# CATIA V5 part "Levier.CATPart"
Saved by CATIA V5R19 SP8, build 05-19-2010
Part number: Levier
Nomenclature: 4
Bounding box of the stored display mesh (mm): x -228 to 228, y -20.3 to 246.7, z -26.3 to 20.3
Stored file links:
  C:\Users\rphgr\Desktop\0_Tapis_TC520B_vitesse\Levier.CATPart
  D:\Documents\1_Travail\1 - ac-limoges.fr\ac-limoges.fr\Emmanuel Maynard - STI2D_Turgot\3 - Supports\Tapis de course TC520B\Tapis de course TC520B_Ca\0_Tapis_TC520B.CATProduct
  D:\Documents\1_Travail\1 - ac-limoges.fr\ac-limoges.fr\Emmanuel Maynard - STI2D_Turgot\3 - Supports\Tapis de course TC520B\Tapis de course TC520B_Ca\CE_Ecrou_Verin.CATPart
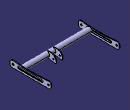
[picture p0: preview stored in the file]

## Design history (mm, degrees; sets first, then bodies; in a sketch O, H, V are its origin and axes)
SheetMetalParameters1: Thickness 5, BendRadius 4, KFactor 0.30103 {= log(min(100,max(20*SheetMetalParameters1.BendRadius,SheetMetalParameters1.Thickness)/SheetMetalParameters1.Thickness))/log(100)/2}, ReliefRadialLength 1, ReliefAxialLength 2, MinimumBendRadius 0
AxisSystem1: origin (0, 0, 0), X (1, 0, 0), Y (0, 1, 0), Z (0, 0, 1)
Set1
  DatumSurface1
  DatumCurve1
Set2
  Plane1: type Offset, RefPlane YZ plane of AxisSystem1, Offset 225.5, reversed
Body1 (main body)
  Sketch1 on Plane1, origin (-225.5, 0, 0), H (0, 1, 0), V (0, 0, 1)
    point P1 (4.7, 20.3)
    point P2 (113.2, 0)
    line L1 (246.7, 7.3) -> (246.7, -7.3)
    line L2 (233.7, -20.3) -> (-7.3, -20.3)
    line L3 (-20.3, -7.3) -> (-20.3, 7.3)
    line L4 (-7.3, 20.3) -> (4.7, 20.3)
    point P3 (-20.3, -20.3)
    arc A1 centre (113.2, 998.2999) radius 984 from (4.7, 20.3) to (221.7, 20.3) ccw
    point P4 (113.2, 998.2999)
    point P5 (221.7, 20.3)
    point P6 (4.7, 20.3)
    line L5 (221.7, 20.3) -> (233.7, 20.3)
    arc A2 centre (233.7, -7.3) radius 13 from (246.7, -7.3) to (233.7, -20.3) cw
    arc A3 centre (-7.3, -7.3) radius 13 from (-7.3, -20.3) to (-20.3, -7.3) cw
    arc A4 centre (-7.3, 7.3) radius 13 from (-20.3, 7.3) to (-7.3, 20.3) cw
    arc A5 centre (233.7, 7.3) radius 13 from (246.7, 7.3) to (233.7, 20.3) ccw
    distance L1 L3 = 267
    radius A2 = 13
    radius A3 = 13
    radius A4 = 13
    radius A5 = 13
    radius A1 = 984
    distance P4 P2 H = 0
    coincidence: P2 H, L4 P5, L4 L5, L2 P3, L3 P3, P6 P1
    vertical: L1 V, L3 V
    horizontal: L2 H, L4 H, L5 H
    equidistance: L1 L3 P2, L2 L4 P2
    tangency: A2 L1, A2 L2, A3 L2, A3 L3, A4 L3, A4 L4, A5 L1, A5 L5
  Wall1: Thickness 5, Profile Sketch1
  Plane2: type Offset, RefPlane YZ plane of AxisSystem1, Offset 225.5, reversed
  Sketch2 on face of Wall1, origin (-220.5, 0, 0), H (0, 1, 0), V (0, 0, 1)
    construction line L1 (38.2, 0) -> (188.2, 0)
    point P1 (38.2, 0)
    line L2 (38.2, 7) -> (188.2, 7)
    line L3 (188.2, -7) -> (38.2, -7)
    arc A1 centre (188.2, 0) radius 7 from (188.2, 7) to (188.2, -7) cw
    arc A2 centre (38.2, 0) radius 7 from (38.2, -7) to (38.2, 7) cw
    reference intersected line E1 (-20.3, -7.3) -> (-20.3, 7.3) from face of Wall1
    distance L1 L2 = 7
    length L1 = 150
    distance P1 E1 = 58.5
    coincidence: P1 H
    horizontal: L1 H
    tangency: A1 L2, A2 L2, A1 L3, A2 L3
  Sketch3 on face of Wall1, origin (-220.5, 0, 0), H (0, -1, 0), V (0, 0, 1)
    construction line L1 (-188.2, 0) -> (-38.2, 0)
    point P1 (-188.2, 0)
    point P2 (-38.2, 0)
    line L2 (-188.2, 0.5) -> (-38.2, 0.5)
    line L3 (-38.2, -0.5) -> (-188.2, -0.5)
    arc A1 centre (-38.2, 0) radius 0.5 from (-38.2, 0.5) to (-38.2, -0.5) cw
    arc A2 centre (-188.2, 0) radius 0.5 from (-188.2, -0.5) to (-188.2, 0.5) cw
    reference projected arc E1 centre (-38.2, 0) radius 7 from (-38.2, -7) to (-38.2, 7) ccw from Sketch2.A2
    reference projected arc E2 centre (-188.2, 0) radius 7 from (-188.2, 7) to (-188.2, -7) ccw from Sketch2.A1
    distance L1 L2 = 0.5
    coincidence: P1 H
    horizontal: L1 H
    tangency: A1 L2, A2 L2, A1 L3, A2 L3
    concentricity: P2 E1, A2 E2
  d_Stamp1: NewRoot_AttribNormalisation "No Standard", Stamp_FilletRadius 1
  Sketch4 on face of Wall1, origin (-225.5, 0.1839, -4.3322), H (0, 1, 0), V (0, 0, -1)
    point P1 (-0.1839, -4.3322)
    reference projected point E1 (-0.1839, -4.3322) from edge [XY plane of AxisSystem1 | ZX plane of AxisSystem1]
    coincidence: P1 E1
  Hole1: placed by Sketch4, at (-225.5, 0, 0) direction (1, 0, 0), diameter 12, through (limit type 3)
  Sketch5 on face of Wall1, origin (-225.5, 226.4946, 0.7211), H (0, 1, 0), V (0, 0, -1)
    point P1 (3.5054, 0.7211)
    reference intersected line E1 through (0, 0.7211) direction (1, 0) from XY plane of AxisSystem1
    reference projected point E2 (-226.4946, 0.7211) from axis of face of Hole1
    distance E2 P1 = 230
    coincidence: P1 E1
  Hole2: placed by Sketch5, at (-225.5, 230, 0) direction (1, 0, 0), diameter 12, through (limit type 3)
  Mirror1: of the body so far, about YZ plane of AxisSystem1
  Sketch6 on YZ plane of AxisSystem1, origin (0, 0, 0), H (0, 1, 0), V (0, 0, 1)
    circle A1 centre (52.7, 0) radius 16
    point P1 (52.7, 0)
    reference intersected line E1 through (-20.3, 0) direction (0, -1) from face of Wall1
    circle A2 centre (52.7, 0) radius 14
    radius A1 = 16
    distance P1 E1 = 73
    distance A2 A1 = 2
    coincidence: P1 H
  Pad1: profile Sketch6, direction (1, 0, 0), up to the existing solid (limit type 2), opposite side up to the existing solid (limit type 2)
  Plane3: type Offset, RefPlane face of Wall1, Offset 236, reversed
  Sketch7 on Plane3, origin (15.5, 0, 0), H (0, -1, 0), V (0, 0, 1)
    line L1 (-52.7, 20.3) -> (-75.7, 20.3)
    arc A1 centre (-75.7, -15.7) radius 36 from (-75.7, 20.3) to (-111.7, -15.7) ccw
    line L2 (-111.7, -15.7) -> (-111.7, -20.3)
    line L3 (-104.6581, -26.2088) -> (-52.7, -17.0472)
    line L4 (-52.7, -17.0472) -> (-52.7, -16)
    reference projected point E1 (-52.7, 0) from axis of face of Pad1 from Sketch6.A1
    arc A2 centre (-52.7, 0) radius 16 from (-52.7, 16) to (-52.7, -16) ccw
    reference projected arc E2 centre (-52.7, 0) radius 16 from (-38.9101, 8.1141) to (-66.4899, 8.1141) ccw from edge [face of Pad1 from Sketch6.A1 | face of Mirror1]
    point P8 (-52.7, 16)
    line L5 (-52.7, 16) -> (-52.7, 20.3)
    reference projected point E3 (-52.7, 0) from axis of face of Pad1 from Sketch6.A1
    arc A3 centre (-105.7, -20.3) radius 6 from (-111.7, -20.3) to (-104.6581, -26.2088) ccw
    point P11 (-105.7, -20.3)
    reference intersected line E4 through (0, 20.3) direction (-1, 0) from face of Wall1
    reference intersected line E5 through (0, -20.3) direction (1, 0) from face of Wall1
    angle L3 L1 = 10
    distance L2 E3 = 59
    radius A3 = 6
    radius A1 = 36
    horizontal: L1 H
    tangency: A1 L1, L2 A1, A3 L2, A3 L3
    vertical: L4 V, L2 V, L5 V
    coincidence: L4 E1, A2 E2, L4 P8, L4 L5, L1 E4, P11 E5
  Pad2: profile Sketch7, direction (-1, 0, 0), length 4
  RectPattern1: of Pad2, direction 1 instances 2, spacing 41, along axis of face of Pad1 from Sketch6.A1
  Sketch8 on face of RectPattern1, origin (56.5, 0, 0), H (0, 1, 0), V (0, 0, 1)
    circle A1 centre (93.9881, -7.7) radius 5.25
    point P1 (93.9881, -7.7)
    reference projected point E1 (93.9881, -7.7) from edge of DatumCurve1
    radius A1 = 5.25
    coincidence: P1 E1
  Pocket1: profile Sketch8, direction (-1, 0, 0), up to end face of Pad2
  Chamfer1: length 0.5, angle 45, on edge [end face of Pad2 | face of Pocket1 from Sketch8.A1]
